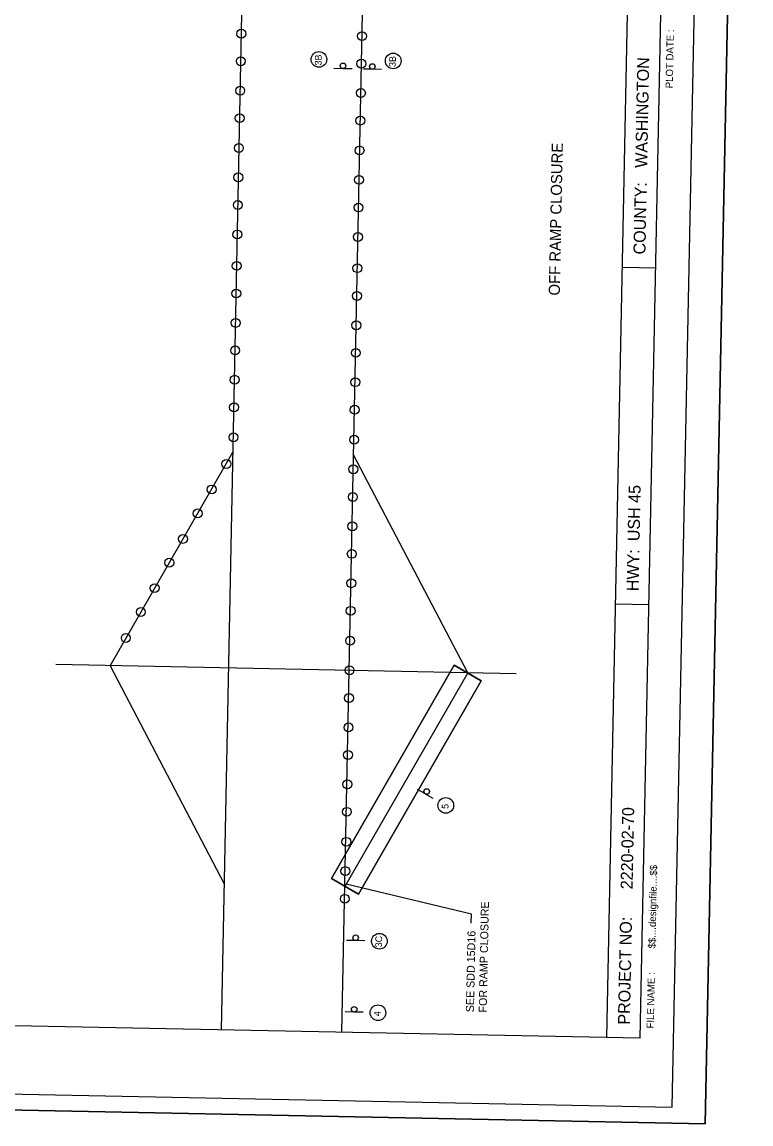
# Model space of a CAD drawing. Extents: x 345549 to 379569, y 127949 to 230467.
# Drawn here: x 363182 to 379569, y 178813 to 203597 of the extents above; entities that cross this region are included whole.
import ezdxf

# ---------------------------------------------------------------- set-up
doc = ezdxf.new("R2010")
doc.units = 0
for name, color, linetype in [('CA-TEXT', 7, 'Continuous'), ('CE-TOPO-CONC-SLAB', 7, 'Continuous'), ('E_RDWY', 7, 'Continuous'), ('P_RDWY_Text', 7, 'Continuous'), ('P_TC', 7, 'Continuous'), ('PLT_Sheet_Border', 7, 'Continuous'), ('PLT_Sheet_Info', 7, 'Continuous'), ('SIGNS-POLES', 7, 'Continuous')]:
    doc.layers.add(name, color=color, linetype=linetype)

msp = doc.modelspace()

# ---------------------------------------------------------------- linework, layer by layer
at = {"layer": 'CA-TEXT'}
for p, q in [((373284, 183534), (370471, 184208)), ((373280, 183329), (373284, 183534))]:
    msp.add_line(p, q, dxfattribs=at)
for centre in [(369857, 202756), (371526, 202723), (372709, 185978), (371216, 182924), (371184, 181315)]:
    msp.add_circle(centre, 176, dxfattribs=at)
at = {"layer": 'CE-TOPO-CONC-SLAB'}
for centre in [(368111, 203334), (370824, 203279), (368100, 202715), (370812, 202660), (368087, 202054), (370800, 202000), (368075, 201435), (370788, 201381), (368057, 200764), (370770, 200709), (368044, 200103), (370757, 200048), (368033, 199480), (370746, 199425), (368021, 198819), (370733, 198764), (368009, 198114), (370722, 198060), (367998, 197491), (370711, 197437), (367986, 196830), (370698, 196776), (367974, 196211), (370686, 196157), (367961, 195551), (370674, 195496), (367949, 194932), (370662, 194877), (367936, 194257), (370649, 194203), (367774, 193657), (370631, 193538), (367444, 193084), (370620, 192915), (367132, 192545), (370607, 192254), (366802, 191972), (370595, 191635), (366492, 191436), (366162, 190864), (370583, 190975), (365853, 190328), (370571, 190355), (365515, 189743), (370558, 189681), (370545, 189016), (370534, 188393), (370521, 187732), (370510, 187113), (370497, 186453), (370485, 185834), (370472, 185159), (370449, 184500), (370438, 183877)]:
    msp.add_circle(centre, 100, dxfattribs=at)
at = {"layer": 'E_RDWY'}
for p, q in [((367663, 180930), (368421, 218579)), ((370375, 180875), (371134, 218525)), ((365163, 189120), (367924, 193921)), ((373203, 188958), (370637, 193866)), ((374289, 188936), (363943, 189144)), ((365163, 189120), (367729, 184211)), ((373203, 188958), (370441, 184157))]:
    msp.add_line(p, q, dxfattribs=at)
at = {"layer": 'P_RDWY_Text'}
msp.add_lwpolyline([(345549, 179477), (346576, 230467), (379569, 229803), (378542, 178813)], close=True, dxfattribs=at)
at = {"layer": 'P_TC'}
for points in [[(370137, 184331), (372899, 189133), (373507, 188783), (370745, 183982), (370137, 184331)], [(370745, 183982), (373507, 188783), (372899, 189133), (370137, 184331), (370745, 183982)]]:
    msp.add_lwpolyline(points, dxfattribs=at)
at = {"layer": 'PLT_Sheet_Border'}
for points in [[(378542, 178813), (379569, 229803), (346576, 230467), (345549, 179477)], [(377800, 179188), (378799, 228828), (347306, 229462), (346306, 179822)]]:
    msp.add_lwpolyline(points, close=True, dxfattribs=at)
at = {"layer": 'PLT_Sheet_Info'}
for p, q in [((376331, 180755), (377282, 227996)), ((377081, 180740), (378032, 227981)), ((377430, 198062), (376680, 198077)), ((377277, 190488), (376527, 190503)), ((377081, 180740), (347087, 181344)), ((378542, 178813), (378573, 180313)), ((378542, 178813), (377043, 178843))]:
    msp.add_line(p, q, dxfattribs=at)
at = {"layer": 'SIGNS-POLES'}
for p, q in [((370398, 202548), (370195, 202552)), ((370602, 202544), (370399, 202547)), ((371059, 202535), (370856, 202539)), ((371262, 202531), (371060, 202534)), ((372251, 186236), (372076, 186338)), ((372427, 186133), (372251, 186234)), ((370683, 182938), (370480, 182943)), ((370887, 182934), (370684, 182937)), ((370650, 181329), (370448, 181333)), ((370854, 181325), (370652, 181328))]:
    msp.add_line(p, q, dxfattribs=at)
for centre in [(370397, 202611), (371057, 202597), (372280, 186291), (370682, 183001), (370649, 181391)]:
    msp.add_circle(centre, 62.6, dxfattribs=at)

# ---------------------------------------------------------------- texts
at = {"layer": 'CA-TEXT'}
for s, height, p in [('3B', 150, (369915, 202619)), ('3B', 150, (371583, 202585)), ('OFF RAMP CLOSURE', 250, (375272, 197443)), ('5', 150, (372768, 185898)), ('FOR RAMP CLOSURE', 180, (373629, 181318)), ('3C', 150, (371273, 182785)), ('SEE SDD 15D16', 180, (373341, 181324)), ('4', 150, (371242, 181235))]:
    msp.add_text(s, height=height, rotation=88.8468, dxfattribs=at).set_placement(p)
at = {"layer": 'PLT_Sheet_Info'}
for s, height, p in [('PLOT DATE :', 162, (377811, 202105)), ('WASHINGTON            ', 270, (377235, 200316)), ('COUNTY:', 270, (377196, 198367)), ('USH 45         ', 270, (377066, 191918)), ('HWY:', 270, (377043, 190793)), ('2220-02-70', 270, (376908, 184089)), ('$$....designfile....$$', 162, (377422, 182759)), ('PROJECT NO:', 270, (376847, 181045)), ('FILE NAME :', 162, (377385, 180959))]:
    msp.add_text(s, height=height, rotation=88.8462, dxfattribs=at).set_placement(p)

doc.saveas('drawing.dxf')
